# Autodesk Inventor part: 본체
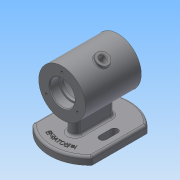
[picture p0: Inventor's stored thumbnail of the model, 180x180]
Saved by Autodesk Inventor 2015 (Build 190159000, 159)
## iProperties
Created: 2022-02
Part Number: 본체
Material: 일반
Document SubType Name: Modeling
Designer: 학생용
Density: 1 g/cm^3
Appearance: 기본값
Author: 학생용
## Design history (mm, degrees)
sketch "스케치1"
  geometry: L1 (0, 0)-(72, 0); L2 (0, 0)-(0, 30); L3 (0, 30)-(72, 30); L4 (72, 30)-(72, 0); L5 (0, 16)-(12, 16); L6 (12, 16)-(12, 14); L7 (12, 14)-(16, 14); L8 (16, 14)-(16, 25); L9 (16, 25)-(56, 25); L10 (56, 25)-(56, 14); L11 (56, 14)-(60, 14); L12 (60, 14)-(60, 16); L13 (60, 16)-(72, 16)
  constraints: 26 end point, 8 perpendicular, 6 point on line, 2 horizontal, 1 collinear, 1 vertical
  dimensions: "d0" = 72 distance of L1.start L1.end; "d1" = 60 diameter of L3 L1; "d2" = 40 distance of L8.end L9.end; "d3" = 12 distance of L5.start L5.end; "d4" = 4 distance of L6.end L7.end; "d5" = 50 diameter of L9 L1; "d6" = 28 diameter of L7 L1; "d7" = 32 diameter of L5 L1
revolve "회전1" sketch "스케치1" stored, may be unused: angle "d8" = 90 deg
chamfer "모따기1" distance "d9" = 1; stored, may be unused: second distance "d10" = 2, angle "d11" = 45 deg
fillet "모깎기1" dims "d12" = 3
fillet "모깎기2" dims "d13" = 0.3
node "작업 평면1"
sketch "스케치2"
  geometry: L1 (0, 0)-(0, 30); L2 (0, 0)-(30, 0); L3 (0, 0)-(16.5, 28.579); A1 r 30 centre (0, 0) between (0, 30) and (30, 0) reference
  constraints: 6 end point, 2 point on circle, 1 perpendicular, 1 vertical
  dimensions: "d14" = 30 deg angle of L1 L3; "d15" = 33 distance of L3.start L3.end
node "작업 평면2"
sketch "스케치3"
  geometry: C1 r 8 at (0, 0); 1 further point
  constraints: 1 centre point
  dimensions: "d16" = 16 diameter of C1
extrude "돌출1" join sketch "스케치3" stored distance "d17" = 10; taper "d18" = 0 deg
sketch "스케치4"
  geometry: C1 r 4 at (0, 0); 1 further point
  constraints: 1 centre point
  dimensions: "d19" = 8 diameter of C1
extrude "돌출2" cut sketch "스케치4" stored distance "d20" = 10; taper "d21" = 0 deg
fillet "모깎기3" dims "d22" = 1
sketch "스케치5"
  geometry: L1 (0, 0)-(-23, 0); L2 (0, 0)-(23, 0); L3 (0, 0)-(19.919, -11.5); L4 (0, 0)-(-19.919, -11.5); A1 r 23 centre (0, 0) between (0, 23) and (-23, 0); 3 further points
  constraints: 8 end point, 5 point on circle, 3 coincident, 2 horizontal, 1 centre point
  dimensions: "d26" = 46 diameter of A1; "d27" = 30 deg angle of L1 L4; "d28" = 30 deg angle of L2 L3
hole "구멍1" sketch "스케치5" at (0, 23), (-19.919, -11.5), (19.919, -11.5) diameter "d29" = 3.242; stored, may be unused: countersink angle "d33" = 90 deg, drill point angle "d35" = 118 deg; dims "d30" = 8, "d31" = 4, "d32" = 2, "d34" = 10
node "작업 평면3"
sketch "스케치6"
  geometry: L1 (42, 36)-(-42, 36) reference; L2 (-38, 0.504)-(-38, 71.496); L3 (38, 71.496)-(38, 0.504); A1 r 52 centre (0, 36) between (-38, 0.504) and (38, 0.504); A2 r 52 centre (0, 36) between (38, 71.496) and (-38, 71.496); 1 further point
  constraints: 4 end point, 4 point on circle, 2 centre point, 1 midpoint, 1 parallel, 1 vertical, 1 vertical alignment
  dimensions: "d38" = 76 distance between parallel lines of L3 L2; "d39" = 38 distance from line of A1.centre L3
extrude "돌출3" join sketch "스케치6" distance "d40" = 10; taper "d41" = 0 deg
sketch "스케치7"
  geometry: L1 (-38, 0.504)-(-38, 71.496) reference; L2 (0, 55)-(0, 17); L3 (-7, 55)-(-7, 17); L4 (7, 17)-(7, 55); L5 (-24, 43.5)-(-24, 28.5); L6 (-28.5, 43.5)-(-28.5, 28.5); L7 (-19.5, 28.5)-(-19.5, 43.5); L8 (24, 43.5)-(24, 28.5); L9 (19.5, 43.5)-(19.5, 28.5); L10 (28.5, 28.5)-(28.5, 43.5); C1 r 42.5 at (0, 36); A1 r 7 centre (0, 55) between (7, 55) and (-7, 55); A2 r 7 centre (0, 17) between (-7, 17) and (7, 17); A3 r 4.5 centre (-24, 43.5) between (-19.5, 43.5) and (-28.5, 43.5); A4 r 4.5 centre (-24, 28.5) between (-28.5, 28.5) and (-19.5, 28.5); A5 r 4.5 centre (24, 43.5) between (28.5, 43.5) and (19.5, 43.5); A6 r 4.5 centre (24, 28.5) between (19.5, 28.5) and (28.5, 28.5); 4 further points
  constraints: 24 end point, 12 point on circle, 12 tangent, 7 centre point, 5 parallel, 4 midpoint, 3 horizontal alignment, 2 vertical, 1 vertical alignment, 1 other
  dimensions: "d42" = 85 diameter of C1; "d43" = 14 distance between parallel lines of L4 L3; "d44" = 38 distance of L2.start L2.end; "d45" = 15 distance of L5.start L5.end; "d46" = 9 distance between parallel lines of L7 L6; "d47" = 9 distance between parallel lines of L10 L9; "d48" = 48 distance between parallel lines of L8 L5; "d49" = 24 distance between parallel lines of L2 L8
extrude "돌출4" cut sketch "스케치7" distance "d50" = 10; taper "d51" = 0 deg
extrude "돌출5" join sketch "스케치7" stored distance "d52" = 10; taper "d53" = 0 deg
feature "엠보싱1" dims "d0" = 72, "d1" = 60, "d2" = 40, "d3" = 12, "d4" = 4, "d5" = 50, "d6" = 28, "d7" = 32, "d54" = 0.5, "d55" = 0
fillet "모깎기4" dims "d56" = 3
fillet "모깎기5" dims "d57" = 3
fillet "모깎기6" dims "d58" = 3
fillet "모깎기7" dims "d59" = 1
node "솔리드1"
mirror "대칭1"
other parameters: "d36" = -62, "d37" = 104
